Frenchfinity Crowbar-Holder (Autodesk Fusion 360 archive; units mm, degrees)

design "Crowbar-Holder" references "Base"
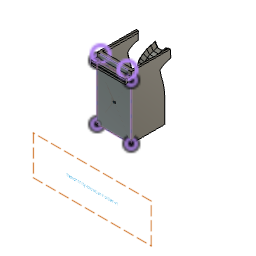
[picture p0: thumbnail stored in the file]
canvas "Canvas1"
sketch "Crowbar" plane through (0, 0, 0) normal (0, 1, 0) x axis (1, 0, 0)
  curve K1 (16, 63.0003) -> (-10, -19)
  curve K2 (34, 68) -> (-9.4189, -32.4164)
  curve K3 (2, -31) -> (-20.8379, -33.8327)
  line L1 (-10, -19) -> (-9.4189, -32.4164)
  line L2 (33.9629, 63.0003) -> (16, 63.0003)
  curve K4 (33.3578, 48.7031) -> (39.3178, 24.3477)
  curve K5 (2, -16) -> (-22, -22)
  curve K6 (23.0087, -3.4965) -> (4.9913, -16.5035)
  curve K7 (17.5692, 34.2662) -> (23.5165, 13.4506)
  curve K8 (32.9127, 49.5608) -> (35.158, 42.3075)
  point P8 (-9.4189, -32.4164)
  point P17 (33.9629, 63.0003)
  point P12 (36.3378, 36.5254)
  point P2 (-10, -19)
  point P3 (14, -10)
  point P5 (20.5429, 23.8584)
  point P13 (34.0354, 45.9341)
  midpoint P8 K3
  coincident K2 P17
  horizontal L2
  midpoint P12 K4
  midpoint P2 K5
  midpoint P3 K6
  midpoint P5 K7
  midpoint P13 K8
  coincident P13 K4
sketch "Holder" plane through (0, 0, 0) normal (0, 1, 0) x axis (1, 0, 0)
  line L1 (33.9629, 63.0003) -> (16, 63.0003)
  curve K1 (16, 63.0003) -> (-10, -19)
  line L2 (-10, -19) -> (-9.4189, -32.4164)
  curve K2 (34, 68) -> (-9.4189, -32.4164)
  line L3 (33.9629, 65.0003) -> (14.0747, 65.0003)
  curve K3 (14.0747, 65.0003) -> (-12.0688, -17.4556)
  line L4 (-12.0688, -17.4556) -> (-11.3233, -34.6679)
  curve K4 (36, 67.986) -> (-11.3233, -34.6679)
  line L5 (-10.0883, -16.9609) -> (-10, -19)
  line L6 (13.9986, 63.0003) -> (16, 63.0003)
  line L7 (-9.3321, -34.4209) -> (-9.4189, -32.4164)
  line L8 (35.9783, 65.0003) -> (33.9629, 65.0003)
  line L9 (35.9629, 63.0003) -> (33.9629, 63.0003)
  line L10 (33.9629, 73.0003) -> (6.3733, 73.0003)
  curve K5 (6.3733, 73.0003) -> (-20.3438, -11.2782)
  line L11 (-20.3438, -11.2782) -> (-18.9407, -43.6741)
  curve K6 (43.8182, 48.1303) -> (-18.9407, -43.6741)
  curve K7 (43.9998, 67.9301) -> (43.8182, 48.1303)
  line L12 (-10.4414, -8.8095) -> (-10.0883, -16.9609)
  line L13 (-8.9848, -42.4392) -> (-9.3321, -34.4209)
  line L14 (5.9931, 63.0003) -> (13.9986, 63.0003)
  line L15 (43.9632, 63.0003) -> (35.9629, 63.0003)
  line L16 (51.1083, -3.7697) -> (43.731, 0.4545)
  line L17 (41.8479, 1.5328) -> (43.731, 0.4545)
  line L18 (33.9629, 79.0003) -> (0.5973, 79.0003)
  curve K8 (0.5973, 79.0003) -> (8.1632, 5.9207)
  curve K9 (8.1632, 5.9207) -> (-26.5501, -6.6451)
  line L19 (-26.5501, -6.6451) -> (-24.6538, -50.4287)
  curve K10 (49.8231, 48.9354) -> (-24.6538, -50.4287)
  curve K11 (49.9996, 67.8881) -> (49.8231, 48.9354)
  line L20 (-10.706, -2.6999) -> (-10.4414, -8.8095)
  line L21 (-0.0108, 63.0003) -> (5.9931, 63.0003)
  point P4 (-10, -19)
  point P12 (-10, -19)
  point P13 (-10.0883, -16.9609)
  point P2 (16, 63.0003)
  point P14 (16, 63.0003)
  point P15 (13.9986, 63.0003)
  point P5 (-9.4189, -32.4164)
  point P16 (-9.4189, -32.4164)
  point P17 (-9.3321, -34.4209)
  point P18 (35.9783, 65.0003)
  point P3 (33.9629, 63.0003)
  point P19 (33.9629, 63.0003)
  point P20 (35.9629, 63.0003)
  point P27 (-10.4414, -8.8095)
  point P28 (-8.9848, -42.4392)
  point P29 (5.9931, 63.0003)
  point P30 (43.9632, 63.0003)
  point P31 (43.731, 0.4545)
  point P32 (51.1083, -3.7697)
  point P33 (41.8479, 1.5328)
  point P41 (-10.706, -2.6999)
  point P42 (-0.0108, 63.0003)
  coincident P4 P12
  coincident K3 P13
  parallel L4 L5
  coincident P2 P14
  coincident K3 P15
  parallel L1 L6
  coincident P5 P16
  coincident K4 P17
  parallel L2 L7
  coincident K4 P18
  parallel L3 L8
  coincident P3 P19
  coincident K4 P20
  parallel L1 L9
  coincident K5 P27
  parallel L5 L12
  coincident K6 P28
  parallel L7 L13
  coincident K5 P29
  parallel L6 L14
  coincident K7 P30
  parallel L9 L15
  coincident K4 P31
  coincident K6 P32
  coincident K2 P33
  parallel L16 L17
  coincident K9 P41
  parallel L12 L20
  coincident K8 P42
  parallel L14 L21
  dimension "d2" = -2
  dimension "d3" = -10
  dimension "d14" = -16
extrude "Extrude1" new body sketch "Holder" profile of K2 K4 K3 L9 K7 K5 L12 L14 L15 L16 L17 K9 L20 L21 along normal blind 22
sketch "Sketch3" plane through (-10.8026, 0, 0.4679) normal (-0.9991, 0, 0.0433) x axis (0, -1, 0)
  line L1 (0, 16.5085) -> (0, 2.2341)
  line L2 (-22, 16.5085) -> (0, 16.5085)
  line L3 (-22, 2.2341) -> (-22, 16.5085)
  line L4 (-11, 8.3494) -> (-11, 16.5085)
  line L5 (-11, 29.9609) -> (-11, 16.5085)
  line L6 (-11, 8.3494) -> (-11, 18.8494)
  line L7 (-0.3768, 18.8494) -> (-5.6884, 9.6494)
  line L8 (-5.6884, 28.0494) -> (-0.3768, 18.8494)
  line L9 (-16.3116, 28.0494) -> (-5.6884, 28.0494)
  line L10 (-21.6232, 18.8494) -> (-16.3116, 28.0494)
  line L11 (-16.3116, 9.6494) -> (-21.6232, 18.8494)
  line L12 (-5.6884, 9.6494) -> (-16.3116, 9.6494)
  line L13 (0, 2.2341) -> (-22, 2.2341)
  point P6 (-11, 16.5085)
  point P9 (-11, 18.8494)
  point P16 (-11, 18.8494)
  point P7 (-11, 8.3494)
  midpoint L2 P6
  perpendicular L2 L5
  coincident L5 P9
  coincident P9 P16
  dimension "d6" distance P7 P9 = 10.5
  dimension "d7" distance P16 L12 = 9.2
sweep "Sweep1" sketch "Sketch3" TwistAngle 0 TaperAngle 0
sketch "Sketch4" plane through (0, 22, 0) normal (0, 1, 0) x axis (-1, 0, 0)
  curve K1 (-43.8182, -48.1303) -> (-51.1083, 3.7697)
  curve K2 (-43.9632, -63.0003) -> (-43.8182, -48.1303)
  line L1 (-33.9629, -63.0003) -> (-43.9632, -63.0003)
  curve K3 (-41.8479, -1.5328) -> (-33.9629, -63.0003)
  line L2 (-51.1083, 3.7697) -> (-41.8479, -1.5328)
  curve K4 (-13.9986, -63.0003) -> (10.0883, 16.9609)
  line L3 (0.0108, -63.0003) -> (-13.9986, -63.0003)
  curve K5 (-8.1632, -5.9207) -> (0.0108, -63.0003)
  curve K6 (10.706, 2.6999) -> (-8.1632, -5.9207)
  line L4 (10.0883, 16.9609) -> (10.706, 2.6999)
  line L5 (-59.0437, 16.9609) -> (10.0883, 16.9609)
  line L6 (-43.9632, -63.0003) -> (0.0108, -63.0003)
  line L7 (-77.0255, -63.0003) -> (-43.9632, -63.0003)
  line L8 (-59.0437, -63.0003) -> (-59.0437, 16.9609)
  point P7 (10.0883, 16.9609)
  point P12 (10.0883, 16.9609)
  point P9 (0.0108, -63.0003)
  point P14 (0.0108, -63.0003)
  point P4 (-43.9632, -63.0003)
  point P15 (-43.9632, -63.0003)
  point P16 (-43.9632, -63.0003)
  point P18 (-59.0437, -63.0003)
  coincident P7 P12
  horizontal L5
  coincident P9 P14
  coincident P4 P15
  coincident P4 P16
  parallel L1 L7
  coincident L7 P18
  perpendicular L7 L8
extrude "Extrude2" add sketch "Sketch4" along normal blind 5
sketch "Sketch5" plane through (0, 22, 0) normal (0, -1, 0) x axis (1, 0, 0)
  curve K1 (13.9986, -63.0003) -> (-10.0883, 16.9609)
  line L1 (33.9629, -63.0003) -> (13.9986, -63.0003)
  curve K2 (41.8479, -1.5328) -> (33.9629, -63.0003)
  line L2 (51.1083, 3.7697) -> (41.8479, -1.5328)
  curve K3 (43.8182, -48.1303) -> (51.1083, 3.7697)
  curve K4 (43.9632, -63.0003) -> (43.8182, -48.1303)
  line L3 (59.0437, -63.0003) -> (43.9632, -63.0003)
  line L4 (59.0437, 16.9609) -> (59.0437, -63.0003)
  line L5 (-10.0883, 16.9609) -> (59.0437, 16.9609)
  curve K5 (43.8182, -48.1303) -> (51.1083, 3.7697)
  line L6 (41.8479, -1.5328) -> (51.1083, 3.7697)
  curve K6 (33.9629, -63.0003) -> (41.8479, -1.5328)
  line L7 (43.9632, -63.0003) -> (33.9629, -63.0003)
  curve K7 (43.9632, -63.0003) -> (43.8182, -48.1303)
  line L8 (51.1083, 16.9609) -> (51.1083, 3.7697)
  point P11 (51.1083, 3.7697)
  point P16 (51.1083, 3.7697)
  point P17 (51.1083, 16.9609)
  coincident P11 P16
  coincident L5 P17
  perpendicular L5 L8
extrude "Extrude3" add sketch "Sketch5" profile of K3 K4 L3 L4 L5 K5 K7 L8 along normal blind 50
extrude "Extrude4" add of existing geometry to an object
sketch "Sketch6" plane through (0, -28, 0) normal (0, -1, 0) x axis (1, 0, 0)
  line L1 (59.0437, -63.0003) -> (33.9629, -63.0003)
  line L2 (59.0437, 16.9609) -> (59.0437, -63.0003)
  line L3 (51.1083, 16.9609) -> (59.0437, 16.9609)
  line L4 (51.1083, 3.7697) -> (51.1083, 16.9609)
  line L5 (41.8479, -1.5328) -> (51.1083, 3.7697)
  curve K1 (41.8479, -1.5328) -> (33.9629, -63.0003)
  curve K2 (8.1632, -5.9207) -> (-0.0108, -63.0003)
  curve K3 (-10.706, 2.6999) -> (8.1632, -5.9207)
  line L6 (-10.0883, 16.9609) -> (-10.706, 2.6999)
  line L7 (59.0437, 16.9609) -> (-10.0883, 16.9609)
  line L8 (59.0437, -63.0003) -> (59.0437, 16.9609)
  line L9 (-0.0108, -63.0003) -> (59.0437, -63.0003)
extrude "Extrude5" add sketch "Sketch6" along normal blind 5
fillet "Fillet1" radius 2
component_insert "Component Insert"
sketch "Sketch7" plane through (0, 55.6118, 0) normal (0, 1, 0) x axis (-1, 0, 0)
  line L1 (0, 52.6059) -> (-47, 52.6059)
  line L2 (0, 60) -> (0, 52.6059)
  line L3 (-47, 60) -> (0, 60)
  line L4 (-47, 52.6059) -> (-47, 60)
  line L5 (-47, 60) -> (0, 60)
move "Move1"
move "Move2"
extrude "Extrude6" add of existing geometry to an object
extrude "Extrude7" add of existing geometry to an object
extrude "Extrude8" add of existing geometry blind 30
sketch "Text" plane through (0, 55.6118, 0) normal (0, -1, 0) x axis (1, 0, 0)
  dimension "d31" = 3
extrude "Extrude9" cut sketch "Text" against normal blind 2
sketch "Filename" plane through (0, 0, 0) normal (0, 1, 0) x axis (1, 0, 0)
  dimension "d34" = 5

design "Base"
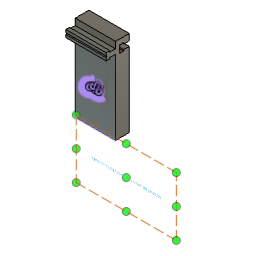
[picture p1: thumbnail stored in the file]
parameter "wall_anchor_height" = 60
parameter "wall_anchor_width" = 20
parameter "wall_anchor_angle" = 45
parameter "width_per_slot" = 40
parameter "slot_inner_width" = 8.5
parameter "slot_inner_height" = 4.5
parameter "slot_outer_width" = 5.6
parameter "slot_outer_height" = 6.5
parameter "slot_dept" = 15
parameter "print_tolerance" = 0.12
parameter "base_plate_thickness" = 16
parameter "base_plate_slot_height" = 50
parameter "wall_anchor_angle_rounded_border" = 1.5
parameter "base_plate_screw_hole_diameter" = 4
parameter "base_plate_screw_head_diameter" = 8
parameter "base_plate_screw_head_height" = 4
parameter "base_plate_screw_hole_side_distance" = 7
parameter "slot_screw_head_width" = 4.42 (= "4.3 mm + print_tolerance")
parameter "slot_screw_thread_width" = 2.12 (= "2 mm + print_tolerance")
parameter "slot_screw_head_height" = 2.12 (= "2 mm + print_tolerance")
parameter "width" = 47
parameter "filament_hole_width" = 1.7
parameter "plate_height" = 80
parameter "screw_plate_screw_head_widht" = 8
parameter "screw_plate_screw_head_height" = 4
parameter "screw_plate_screw_diameter" = 4
parameter "SkadisSlotW_1" = 5 comment "Skadis Slot Width"
parameter "SkadisSlotH_1" = 15 comment "Skadis Slot Height"
parameter "ClearanceHoriz_1" = 0.3 comment "Horizontal clearance for peg"
parameter "ClearanceVerticle_1" = 1 comment "Vertical clearance for peg"
parameter "PegW_1" = 4.7 (= "SkadisSlotW_1 - ClearanceHoriz_1") comment "Calculated Peg Width"
parameter "PegH_1" = 14 (= "SkadisSlotH_1 - ClearanceVerticle_1") comment "Calculated Peg Height"
parameter "PegD_1" = 5.2 (= "5 mm + 0.2 mm")
parameter "SkadisSlotW_2" = 5 comment "Skadis Slot Width"
parameter "SkadisSlotH_2" = 15 comment "Skadis Slot Height"
parameter "ClearanceHoriz_2" = 0.3 comment "Horizontal clearance for peg"
parameter "ClearanceVerticle_2" = 1 comment "Vertical clearance for peg"
parameter "PegW_2" = 4.7 (= "SkadisSlotW_2 - ClearanceHoriz_2") comment "Calculated Peg Width"
parameter "PegH_2" = 14 (= "SkadisSlotH_2 - ClearanceVerticle_2") comment "Calculated Peg Height"
parameter "PegD_2" = 5.2 (= "5 mm + 0.2 mm")
parameter "SkadisSlotW_3" = 5 comment "Skadis Slot Width"
parameter "SkadisSlotH_3" = 15 comment "Skadis Slot Height"
parameter "ClearanceHoriz_3" = 0.3 comment "Horizontal clearance for peg"
parameter "ClearanceVerticle_3" = 1 comment "Vertical clearance for peg"
parameter "PegW_3" = 4.7 (= "SkadisSlotW_3 - ClearanceHoriz_3") comment "Calculated Peg Width"
parameter "PegH_3" = 14 (= "SkadisSlotH_3 - ClearanceVerticle_3") comment "Calculated Peg Height"
parameter "PegD_3" = 5.2 (= "5 mm + 0.2 mm")
sketch "Side" plane through (0, 0, 0) normal (1, 0, 0) x axis (0, 1, 0)
  line L1 (39.6118, 0) -> (19.6118, 0)
  line L2 (39.6118, 60) -> (39.6118, 0)
  line L3 (19.6118, 60) -> (39.6118, 60)
  line L4 (19.6118, 0) -> (19.6118, 60)
  line L5 (39.6118, 39.6118) -> (0, 0)
  line L6 (56.0196, 0) -> (0, 0)
  point P1 (0, 0)
  point P6 (0, 0)
  point P7 (39.6118, 39.6118)
  point P2 (19.6118, 0)
  point P3 (39.6118, 0)
  point P5 (19.6118, 60)
  horizontal L1
  vertical L2
  horizontal L3
  vertical L4
  horizontal L6
  coincident P1 P6
  coincident L2 P7
  dimension "d4" distance P2 P3 = 20 (= "wall_anchor_width")
  dimension "d5" distance P2 P5 = 60 (= "wall_anchor_height")
  dimension "d6" angle L5 L6 = 45 (= "wall_anchor_angle")
extrude "Extrude1" new body sketch "Side" profile of L1 L2 L3 L4 L5 along normal blind 40 (= "width_per_slot")
sketch "Slot LeftToRight" plane through (0, 0, 0) normal (-1, 0, 0) x axis (0, -1, 0)
  line L1 (-19.6118, 60) -> (-19.6118, 19.6118)
  line L2 (-39.6118, 60) -> (-19.6118, 60)
  line L3 (-39.6118, 39.6118) -> (-39.6118, 60)
  line L4 (-19.6118, 19.6118) -> (-39.6118, 39.6118)
  line L5 (-39.6118, 52.6059) -> (-39.6118, 49.8059)
  line L6 (-39.6118, 47.0059) -> (-39.6118, 49.8059)
  line L7 (-33.1118, 52.6059) -> (-39.6118, 52.6059)
  line L8 (-28.6118, 49.8059) -> (-39.6118, 49.8059)
  line L9 (-28.6118, 54.0559) -> (-28.6118, 49.8059)
  line L10 (-33.1118, 54.0559) -> (-28.6118, 54.0559)
  line L11 (-33.1118, 52.6059) -> (-33.1118, 54.0559)
  line L12 (-28.6118, 45.5559) -> (-28.6118, 49.8059)
  line L13 (-33.1118, 45.5559) -> (-28.6118, 45.5559)
  line L14 (-33.1118, 47.0059) -> (-33.1118, 45.5559)
  line L15 (-33.1118, 47.0059) -> (-39.6118, 47.0059)
  point P6 (-39.6118, 49.8059)
  point P7 (-39.6118, 52.6059)
  point P17 (-39.6118, 47.0059)
  point P9 (-33.1118, 52.6059)
  point P16 (-33.1118, 47.0059)
  point P10 (-28.6118, 49.8059)
  point P13 (-28.6118, 49.8059)
  point P11 (-28.6118, 54.0559)
  point P14 (-28.6118, 45.5559)
  point P12 (-33.1118, 54.0559)
  point P15 (-33.1118, 45.5559)
  midpoint L3 P6
  parallel L3 L5
  parallel L3 L6
  perpendicular L3 L7
  perpendicular L6 L8
  perpendicular L8 L9
  perpendicular L9 L10
  symmetric P7 L8 P17
  symmetric P9 L8 P16
  symmetric P10 L8 P13
  symmetric L8 P11 P14
  symmetric L8 P12 P15
  dimension "d80" distance P6 P7 = 2.8 (= "slot_outer_width / 2")
  dimension "d82" distance P7 P9 = 6.5 (= "slot_outer_height")
  dimension "d84" distance P6 P10 = 11 (= "slot_outer_height + slot_inner_height")
  dimension "d85" distance P10 P11 = 4.25 (= "slot_inner_width / 2")
  dimension "d86" distance P11 P12 = 4.5 (= "slot_inner_height")
extrude "Extrude3" cut sketch "Slot LeftToRight" profile of L3 L5 L6 L7 L9 L10 L11 L12 L13 L14 L15 against normal blind 40 (magnitude of "width_per_slot * -1")
sketch "Plate" plane through (0, 39.6118, 0) normal (0, 1, 0) x axis (-1, 0, 0)
  line L1 (0, 39.6118) -> (-40, 39.6118)
  line L2 (-40, 60) -> (0, 60)
  line L3 (0, 10) -> (0, 60)
  line L4 (-40, 10) -> (-40, 60)
  line L5 (-40, 10) -> (0, 10)
  line L6 (-40, 47.0059) -> (0, 47.0059)
  line L7 (-40, 52.6059) -> (-40, 60)
  line L8 (0, 60) -> (0, 52.6059)
  line L9 (0, 52.6059) -> (-40, 52.6059)
  line L10 (-40, 60) -> (0, 60)
  line L11 (-40, 39.6118) -> (-40, 47.0059)
  line L12 (0, 47.0059) -> (0, 39.6118)
  point P2 (0, 60)
  point P3 (-40, 60)
  point P4 (0, 10)
  point P5 (-40, 10)
  perpendicular L1 L3
  perpendicular L1 L4
  dimension "d36" distance P2 P3 = 40 (= "width_per_slot")
  dimension "d37" distance P2 P4 = 50 (= "base_plate_slot_height")
  dimension "d39" distance P3 P5 = 50 (= "base_plate_slot_height")
extrude "Extrude6" new body sketch "Plate" profile of L1 L2 L3 L4 L5 L6 L7 L8 L9 L10 along normal blind 16 (= "base_plate_thickness") bodies "Base plate with slot"
sketch "Slot" plane through (0, 0, 0) normal (-1, 0, 0) x axis (0, -1, 0)
  line L1 (-19.6118, 60) -> (-19.6118, 19.6118)
  line L2 (-39.6118, 60) -> (-19.6118, 60)
  line L3 (-39.6118, 52.6059) -> (-39.6118, 60)
  line L4 (-33.1118, 52.6059) -> (-39.6118, 52.6059)
  line L5 (-33.1118, 54.0559) -> (-33.1118, 52.6059)
  line L6 (-28.6118, 54.0559) -> (-33.1118, 54.0559)
  line L7 (-28.6118, 45.5559) -> (-28.6118, 54.0559)
  line L8 (-33.1118, 45.5559) -> (-28.6118, 45.5559)
  line L9 (-33.1118, 47.0059) -> (-33.1118, 45.5559)
  line L10 (-39.6118, 47.0059) -> (-33.1118, 47.0059)
  line L11 (-39.6118, 39.6118) -> (-39.6118, 47.0059)
  line L12 (-19.6118, 19.6118) -> (-39.6118, 39.6118)
  line L13 (-33.1118, 52.6059) -> (-39.6118, 52.6059)
  line L14 (-33.1118, 54.0559) -> (-33.1118, 52.6059)
  line L15 (-28.6118, 54.0559) -> (-33.1118, 54.0559)
  line L16 (-28.6118, 45.5559) -> (-28.6118, 54.0559)
  line L17 (-33.1118, 45.5559) -> (-28.6118, 45.5559)
  line L18 (-33.1118, 47.0059) -> (-33.1118, 45.5559)
  line L19 (-39.6118, 47.0059) -> (-33.1118, 47.0059)
  line L20 (-39.6118, 10) -> (-39.6118, 60)
  line L21 (-32.9918, 52.4859) -> (-39.6118, 52.4859)
  line L22 (-32.9918, 53.9359) -> (-32.9918, 52.4859)
  line L23 (-28.7318, 53.9359) -> (-32.9918, 53.9359)
  line L24 (-28.7318, 45.6759) -> (-28.7318, 53.9359)
  line L25 (-32.9918, 45.6759) -> (-28.7318, 45.6759)
  line L26 (-32.9918, 47.1259) -> (-32.9918, 45.6759)
  line L27 (-39.6118, 47.1259) -> (-32.9918, 47.1259)
  line L28 (-33.1118, 52.6059) -> (-39.6118, 52.6059)
  line L29 (-33.1118, 52.6059) -> (-33.1118, 54.0559)
  line L30 (-28.6118, 54.0559) -> (-33.1118, 54.0559)
  line L31 (-28.6118, 45.5559) -> (-28.6118, 54.0559)
  line L32 (-33.1118, 45.5559) -> (-28.6118, 45.5559)
  line L33 (-33.1118, 47.0059) -> (-33.1118, 45.5559)
  line L34 (-39.6118, 47.0059) -> (-33.1118, 47.0059)
  line L35 (-39.6118, 47.0059) -> (-39.6118, 52.6059)
  line L36 (-49.1118, 52.6059) -> (-55.6118, 52.6059)
  line L37 (-49.1118, 52.6059) -> (-49.1118, 54.0559)
  line L38 (-44.6118, 54.0559) -> (-49.1118, 54.0559)
  line L39 (-44.6118, 45.5559) -> (-44.6118, 54.0559)
  line L40 (-49.1118, 45.5559) -> (-44.6118, 45.5559)
  line L41 (-49.1118, 47.0059) -> (-49.1118, 45.5559)
  line L42 (-55.6118, 47.0059) -> (-49.1118, 47.0059)
  line L43 (-55.6118, 47.0059) -> (-55.6118, 52.6059)
  point P15 (-39.6118, 52.6059)
  point P33 (-39.6118, 52.6059)
  point P16 (-33.1118, 52.6059)
  point P34 (-33.1118, 52.6059)
  point P17 (-33.1118, 54.0559)
  point P35 (-33.1118, 54.0559)
  point P36 (-33.1118, 52.6059)
  point P18 (-28.6118, 54.0559)
  point P37 (-28.6118, 54.0559)
  point P19 (-28.6118, 45.5559)
  point P38 (-28.6118, 45.5559)
  point P10 (-28.6118, 45.5559)
  point P39 (-28.6118, 45.5559)
  point P11 (-33.1118, 45.5559)
  point P40 (-33.1118, 45.5559)
  point P41 (-33.1118, 45.5559)
  point P12 (-33.1118, 47.0059)
  point P42 (-33.1118, 47.0059)
  point P21 (-33.1118, 47.0059)
  point P43 (-33.1118, 47.0059)
  point P22 (-39.6118, 47.0059)
  point P44 (-39.6118, 47.0059)
  point P45 (-39.6118, 52.6059)
  point P46 (-39.6118, 47.0059)
  coincident P15 P33
  coincident P16 P34
  coincident P17 P35
  coincident P16 P36
  coincident P18 P37
  coincident P19 P38
  coincident P10 P39
  coincident P11 P40
  coincident P11 P41
  coincident P12 P42
  coincident P21 P43
  coincident P22 P44
  coincident P15 P45
  coincident P22 P46
  dimension "d91" = 0.12 (= "print_tolerance")
  dimension "d96" R-Pattern1-uDistance = -16 (= "base_plate_thickness * -1")
  dimension "d97" R-Pattern1-vDistance = 0
extrude "Extrude7" add sketch "Slot" profile of L20 L24 L23 L27 L22 L25 L26 L21 against normal blind 40 (magnitude of "width_per_slot * -1")
extrude "Extrude8" cut sketch "Slot" profile of L36 L37 L38 L39 L40 L41 L42 L43 no distance stored
sketch "Sketch3" plane through (0, 0, 0) normal (-1, 0, 0) x axis (0, -1, 0)
  line L1 (-32.9918, 47.1259) -> (-39.6118, 47.1259)
  line L2 (-32.9918, 45.6759) -> (-32.9918, 47.1259)
  line L3 (-28.7318, 45.6759) -> (-32.9918, 45.6759)
  line L4 (-28.7318, 53.9359) -> (-28.7318, 45.6759)
  line L5 (-32.9918, 53.9359) -> (-28.7318, 53.9359)
  line L6 (-32.9918, 52.4859) -> (-32.9918, 53.9359)
  line L7 (-39.6118, 52.4859) -> (-32.9918, 52.4859)
  line L8 (-44.6118, 45.5559) -> (-44.6118, 54.0559)
  line L9 (-32.9918, 52.4859) -> (-39.6118, 52.4859)
  line L10 (-32.9918, 53.9359) -> (-32.9918, 52.4859)
  line L11 (-28.7318, 53.9359) -> (-32.9918, 53.9359)
  line L12 (-28.7318, 45.6759) -> (-28.7318, 53.9359)
  line L13 (-32.9918, 45.6759) -> (-28.7318, 45.6759)
  line L14 (-32.9918, 47.1259) -> (-32.9918, 45.6759)
  line L15 (-39.6118, 47.1259) -> (-32.9918, 47.1259)
  line L16 (-39.6118, 47.1259) -> (-39.6118, 52.4859)
  line L17 (-55.6118, 52.4859) -> (-48.9918, 52.4859)
  line L18 (-48.9918, 52.4859) -> (-48.9918, 53.9359)
  line L19 (-48.9918, 53.9359) -> (-44.7318, 53.9359)
  line L20 (-44.7318, 45.6759) -> (-44.7318, 53.9359)
  line L21 (-48.9918, 45.6759) -> (-44.7318, 45.6759)
  line L22 (-48.9918, 47.1259) -> (-48.9918, 45.6759)
  line L23 (-55.6118, 47.1259) -> (-48.9918, 47.1259)
  line L24 (-55.6118, 47.1259) -> (-55.6118, 52.4859)
  line L25 (-55.6118, 47.0059) -> (-49.1118, 47.0059)
  line L26 (-55.6118, 10) -> (-55.6118, 47.0059)
  line L27 (-39.6118, 10) -> (-55.6118, 10)
  line L28 (-39.6118, 47.1259) -> (-39.6118, 10)
  line L29 (-39.6118, 60) -> (-39.6118, 52.4859)
  line L30 (-55.6118, 60) -> (-39.6118, 60)
  line L31 (-55.6118, 52.6059) -> (-55.6118, 60)
  line L32 (-49.1118, 52.6059) -> (-55.6118, 52.6059)
  line L33 (-49.1118, 54.0559) -> (-49.1118, 52.6059)
  line L34 (-44.6118, 54.0559) -> (-49.1118, 54.0559)
  line L35 (-49.1118, 45.5559) -> (-44.6118, 45.5559)
  line L36 (-49.1118, 47.0059) -> (-49.1118, 45.5559)
  point P9 (-39.6118, 52.4859)
  point P20 (-39.6118, 52.4859)
  point P19 (-39.6118, 47.1259)
  point P21 (-39.6118, 47.1259)
  coincident P9 P20
  coincident P19 P21
  dimension "d105" R-Pattern1-vDistance = 0
extrude "Extrude3" new body sketch "Sketch3" profile of L17 L18 L19 L20 L21 L22 L23 L24 against normal blind 40 (magnitude of "width_per_slot * -1")
sketch "Screw hole" plane through (0, 28.6118, 0) normal (0, 1, 0) x axis (-1, 0, 0)
  line L1 (0, 54.0559) -> (0, 45.5559)
  line L2 (-40, 54.0559) -> (0, 54.0559)
  line L3 (-40, 45.5559) -> (-40, 54.0559)
  line L4 (0, 45.5559) -> (-40, 45.5559)
  line L5 (0, 45.5559) -> (-40, 54.0559)
  line L6 (-40, 45.5559) -> (0, 54.0559)
  circle C1 centre (-20, 49.8059) radius 2.21
  circle C2 centre (-20, 49.8059) radius 1.06
  point P4 (-40, 54.0559)
  point P6 (-40, 54.0559)
  point P2 (0, 45.5559)
  point P7 (0, 45.5559)
  point P3 (0, 54.0559)
  point P8 (0, 54.0559)
  point P5 (-40, 45.5559)
  point P9 (-40, 45.5559)
  point P10 (-20, 49.8059)
  coincident P4 P6
  coincident P2 P7
  coincident P3 P8
  coincident P5 P9
  midpoint L5 P10
  concentric C1 C2
  dimension "d119" diameter C1 = 4.42 (= "slot_screw_head_width")
  dimension "d120" diameter C2 = 2.12 (= "slot_screw_thread_width")
extrude "Extrude4" cut sketch "Screw hole" profile of C2 against normal blind 2000
extrude "Extrude5" cut sketch "Screw hole" profile of C1 C2 no distance stored
fillet "Fillet1" radius 1.5 (= "wall_anchor_angle_rounded_border")
work_plane "WorkPlane1" sketch "Slot LeftToRight" AlongDistance -20 (= "-width_per_slot / 2")
sketch "Screw head" plane through (20, 0, 0) normal (-1, 0, 0) x axis (0, -1, 0)
  line L1 (-28.6118, 52.0159) -> (-28.6118, 47.5959)
  line L2 (-26.4918, 52.0159) -> (-26.4918, 47.5959)
  line L3 (-26.4918, 48.7459) -> (-26.4918, 50.8659)
  line L4 (-26.4918, 50.8659) -> (-28.6118, 52.0159)
  line L5 (-26.4918, 52.0159) -> (-28.6118, 52.0159)
  point P3 (-28.6118, 52.0159)
  point P8 (-28.6118, 52.0159)
  point P6 (-26.4918, 50.8659)
  point P9 (-26.4918, 50.8659)
  point P10 (-28.6118, 52.0159)
  point P5 (-26.4918, 52.0159)
  point P11 (-26.4918, 52.0159)
  coincident P3 P8
  coincident P6 P9
  coincident P3 P10
  coincident P5 P11
revolve "Revolve1" sketch "Screw head" AlongAngle 360
rectangular_pattern "R-Pattern2" countU 1 (= "floor(( width / mm ) / ( width_per_slot / cm * 10 ))") uSpaceDistance 40 (= "width_per_slot") vSpaceDistance 0
work_plane "WorkPlane2"
extrude "Extrude12" new body of existing geometry no distance stored
mirror "Mirror3" mirrorStitchTolerance 0.1
sketch "filename" plane through (0, 19.6118, 0) normal (0, -1, 0) x axis (1, 0, 0)
  dimension "d216" = 3
sketch "Text" plane through (0, 19.6118, 0) normal (0, -1, 0) x axis (1, 0, 0)
  line L1 (43.5, 60) -> (43.5, 23.2332)
  line L2 (40, 23.2332) -> (40, 60)
  line L3 (43.5, 23.2332) -> (40, 23.2332)
  line L4 (43.5, 60) -> (43.5, 23.2332)
  line L5 (40, 60) -> (43.5, 60)
  line L6 (0, 60) -> (0, 23.2332)
  line L7 (-3.5, 60) -> (0, 60)
  line L8 (-3.5, 23.2332) -> (-3.5, 60)
  line L9 (0, 23.2332) -> (-3.5, 23.2332)
  curve K1
  curve K2
  curve K3
  curve K4
  line L10 (80, 60) -> (40, 60)
  point P4 (43.5, 23.2332)
  point P2 (-3.5, 60)
  coincident P4
  coincident P2
  parallel K3 L10
  dimension "d229" Text1-Height = 3
extrude "Extrude19" cut sketch "Text" against normal blind 2
extrude "Extrude14" cut of existing geometry blind 3.5 (= "( width_per_slot - width ) / -2")
extrude "Extrude15" cut of existing geometry blind 3.5 (= "( width_per_slot - width ) / -2")
extrude "Extrude9" cut of existing geometry blind -39 (= "-width_per_slot + 1 mm")
extrude "Extrude10" add of existing geometry blind 46 (= "width - 1 mm")
extrude "Extrude13" cut of existing geometry blind -30
extrude "Extrude14" add of existing geometry blind 80 (= "plate_height")
sketch "Sketch7" plane through (0, 39.6118, 0) normal (0, -1, 0) x axis (1, 0, 0)
  dimension "d236" = 3
extrude "Extrude11" cut sketch "Sketch7" against normal blind 2
sketch "File name" plane through (0, 39.6118, 0) normal (0, -1, 0) x axis (1, 0, 0)
  line L1 (0, 47.1259) -> (47, 47.1259)
  line L2 (0, -40) -> (0, 47.1259)
  line L3 (47, 47.1259) -> (47, -40)
  curve K1
  curve K2
  curve K3
  curve K4
  line L4 (47, -40) -> (0, -40)
  curve K5 (21.0617, 1.5882) -> (21.4014, 1.3488)
  line L5 (16.2752, -1.111) -> (16.6436, -1.111)
  line L6 (18.9744, -0.2781) -> (18.9744, 0.9108)
  line L7 (18.6061, -0.2781) -> (18.9744, -0.2781)
  curve K6 (20.9512, 1.9606) -> (21.0617, 1.5882)
  curve K7 (21.1866, 2.5111) -> (20.9512, 1.9606)
  line L8 (16.6436, -1.111) -> (16.6436, -0.053)
  curve K8 (16.6436, -0.053) -> (16.883, -0.2495)
  curve K9 (26.9574, -0.0182) -> (27.6388, -0.3293)
  curve K10 (26.6606, 1.2014) -> (26.9574, -0.0182)
  curve K11 (28.1832, -0.1533) -> (28.5085, 0.3481)
  curve K12 (27.6388, -0.3293) -> (28.1832, -0.1533)
  curve K13 (23.4621, -0.0182) -> (24.1436, -0.3293)
  curve K14 (23.1654, 1.2014) -> (23.4621, -0.0182)
  curve K15 (24.5672, 2.6359) -> (24.1436, 2.7342)
  curve K16 (24.868, 2.3556) -> (24.5672, 2.6359)
  curve K17 (25.0542, 1.9095) -> (24.868, 2.3556)
  curve K18 (25.1218, 1.2014) -> (25.0542, 1.9095)
  curve K19 (25.0133, 0.3481) -> (25.1218, 1.2014)
  curve K20 (24.6879, -0.1533) -> (25.0133, 0.3481)
  curve K21 (24.1436, -0.3293) -> (24.6879, -0.1533)
  curve K22 (19.2405, 1.5411) -> (19.5495, 1.6271)
  curve K23 (19.0358, 1.3119) -> (19.2405, 1.5411)
  curve K24 (18.9744, 0.9108) -> (19.0358, 1.3119)
  line L9 (25.7029, 4.404) -> (26.0815, 4.404)
  curve K25 (25.8421, 5.2594) -> (25.7029, 4.404)
  curve K26 (26.2227, 6.2253) -> (25.8421, 5.2594)
  dimension "d239" Text1-Height = 3
sketch "Sketch4" plane through (40, 0, 0) normal (1, 0, 0) x axis (0, 1, 0)
  line L1 (44.7318, 53.9359) -> (48.9918, 53.9359)
  line L2 (44.7318, 45.6759) -> (44.7318, 53.9359)
  line L3 (48.9918, 45.6759) -> (44.7318, 45.6759)
  line L4 (48.9918, 47.1259) -> (48.9918, 45.6759)
  line L5 (55.6118, 47.1259) -> (48.9918, 47.1259)
  line L6 (55.6118, 52.4859) -> (55.6118, 47.1259)
  line L7 (48.9918, 52.4859) -> (55.6118, 52.4859)
  line L8 (48.9918, 53.9359) -> (48.9918, 52.4859)
  circle C1 centre (44.7318, 49.8059) radius 0.85
  point P10 (44.7318, 49.8059)
  midpoint L2 P10
  dimension "d241" diameter C1 = 1.7 (= "filament_hole_width")
extrude "Extrude4" cut sketch "Sketch4" profile of L2 C1 no distance stored
sketch "Sketch15" plane through (-3.5, 0, 0) normal (-1, 0, 0) x axis (0, -1, 0)
  line L1 (-19.6118, 60) -> (-19.6118, 23.2332)
  line L2 (-39.6118, 60) -> (-19.6118, 60)
  line L3 (-39.6118, 52.6059) -> (-39.6118, 60)
  line L4 (-33.1118, 52.6059) -> (-39.6118, 52.6059)
  line L5 (-33.1118, 54.0559) -> (-33.1118, 52.6059)
  line L6 (-28.6118, 54.0559) -> (-33.1118, 54.0559)
  line L7 (-28.6118, 45.5559) -> (-28.6118, 54.0559)
  line L8 (-33.1118, 45.5559) -> (-28.6118, 45.5559)
  line L9 (-33.1118, 47.0059) -> (-33.1118, 45.5559)
  line L10 (-39.6118, 47.0059) -> (-33.1118, 47.0059)
  line L11 (-39.6118, 39.6118) -> (-39.6118, 47.0059)
  line L12 (-22.1725, 22.1725) -> (-39.6118, 39.6118)
  arc A1 centre (-21.1118, 23.2332) radius 1.5 clockwise from (-19.6118, 23.2332) to (-22.1725, 22.1725)
  circle C1 centre (-28.6118, 49.8059) radius 0.85
  point P16 (-28.6118, 49.8059)
  midpoint L7 P16
  dimension "d244" diameter C1 = 1.7 (= "filament_hole_width")
sketch "Sketch9" plane through (47, 0, 0) normal (1, 0, 0) x axis (0, 1, 0)
  line L1 (49.1118, 47.0059) -> (55.6118, 47.0059)
  line L2 (49.1118, 45.5559) -> (49.1118, 47.0059)
  line L3 (44.6118, 45.5559) -> (49.1118, 45.5559)
  line L4 (44.6118, 54.0559) -> (44.6118, 45.5559)
  line L5 (49.1118, 54.0559) -> (44.6118, 54.0559)
  line L6 (49.1118, 52.6059) -> (49.1118, 54.0559)
  line L7 (55.6118, 52.6059) -> (49.1118, 52.6059)
  line L8 (55.6118, 47.0059) -> (55.6118, -40)
  line L9 (39.6118, 60) -> (55.6118, 60)
  line L10 (39.6118, 52.4859) -> (39.6118, 60)
  line L11 (32.9918, 52.4859) -> (39.6118, 52.4859)
  line L12 (32.9918, 53.9359) -> (32.9918, 52.4859)
  line L13 (28.7318, 53.9359) -> (32.9918, 53.9359)
  line L14 (28.7318, 45.6759) -> (28.7318, 53.9359)
  line L15 (32.9918, 45.6759) -> (28.7318, 45.6759)
  line L16 (32.9918, 47.1259) -> (32.9918, 45.6759)
  line L17 (39.6118, 47.1259) -> (32.9918, 47.1259)
  line L18 (55.6118, 60) -> (55.6118, 52.6059)
  line L19 (39.6118, -40) -> (39.6118, 47.1259)
  line L20 (55.6118, -40) -> (39.6118, -40)
  circle C1 centre (28.7318, 49.8059) radius 0.85
  circle C2 centre (44.6118, 49.8059) radius 0.85
  point P20 (28.7318, 49.8059)
  point P21 (44.6118, 49.8059)
  midpoint L14 P20
  midpoint L4 P21
  dimension "d247" diameter C1 = 1.7 (= "filament_hole_width")
  dimension "d250" diameter C2 = 1.7 (= "filament_hole_width")
extrude "Extrude12" cut sketch "Sketch9" profile of L4 L14 C1 C2 no distance stored
sketch "Sketch16" plane through (0, 19.6118, 0) normal (0, -1, 0) x axis (1, 0, 0)
  dimension "d253" = 3
extrude "Extrude22" cut sketch "Sketch16" against normal blind 2
extrude "Extrude23" cut sketch "Sketch15" profile of L7 C1 against normal blind 260 and along normal blind 80
sketch "Sketch17" plane through (0, 19.6118, 0) normal (0, -1, 0) x axis (1, 0, 0)
  line L1 (0, 60) -> (40, 60)
  line L2 (40, 23.2332) -> (0, 23.2332)
  curve K1
  curve K2
  curve K3
  curve K4
  line L3 (40, 60) -> (40, 23.2332)
  line L4 (0, 23.2332) -> (0, 60)
  curve K5 (14.0832, 42.1328) -> (14.4328, 42.3871)
  curve K6 (13.6968, 41.9419) -> (14.0832, 42.1328)
  curve K7 (14.2359, 42.6507) -> (13.6962, 42.2979)
  curve K8 (14.5627, 43.0523) -> (14.2359, 42.6507)
  curve K9 (17.9487, 40.9457) -> (17.8368, 40.4974)
  curve K10 (20.4689, 40.2313) -> (21.1261, 39.997)
  curve K11 (20.1712, 40.8407) -> (20.4689, 40.2313)
  curve K12 (20.755, 40.4384) -> (20.5395, 40.8904)
  curve K13 (21.1277, 40.3019) -> (20.755, 40.4384)
  curve K14 (21.5653, 40.4827) -> (21.1277, 40.3019)
  curve K15 (21.7447, 40.9291) -> (21.5653, 40.4827)
  curve K16 (21.5783, 41.3463) -> (21.7447, 40.9291)
  curve K17 (21.1565, 41.5114) -> (21.5783, 41.3463)
  curve K18 (20.8967, 41.47) -> (21.1565, 41.5114)
  curve K19 (20.9965, 41.7894) -> (20.9371, 41.7934)
  curve K20 (21.4199, 41.9129) -> (20.9965, 41.7894)
  curve K21 (21.6076, 42.2917) -> (21.4199, 41.9129)
  curve K22 (21.4699, 42.6271) -> (21.6076, 42.2917)
  curve K23 (21.1157, 42.7596) -> (21.4699, 42.6271)
  curve K24 (20.7578, 42.624) -> (21.1157, 42.7596)
  curve K25 (20.5742, 42.2185) -> (20.7578, 42.624)
  curve K26 (20.5119, 42.8569) -> (20.2058, 42.2834)
  curve K27 (21.107, 43.0625) -> (20.5119, 42.8569)
  curve K28 (21.5595, 42.9568) -> (21.107, 43.0625)
  curve K29 (21.875, 42.6707) -> (21.5595, 42.9568)
  curve K30 (21.9861, 42.2841) -> (21.875, 42.6707)
  curve K31 (21.8823, 41.93) -> (21.9861, 42.2841)
  curve K32 (21.5737, 41.6757) -> (21.8823, 41.93)
  curve K33 (21.9875, 41.4206) -> (21.5737, 41.6757)
  curve K34 (22.1356, 40.9379) -> (21.9875, 41.4206)
  curve K35 (21.8501, 40.2703) -> (22.1356, 40.9379)
  curve K36 (21.1261, 39.997) -> (21.8501, 40.2703)
  curve K37 (26.2927, 40.3181) -> (26.9747, 40.0081)
  curve K38 (25.9941, 41.5373) -> (26.2927, 40.3181)
  curve K39 (26.1013, 42.3928) -> (25.9941, 41.5373)
  curve K40 (26.4259, 42.8947) -> (26.1013, 42.3928)
  curve K41 (26.9699, 43.0715) -> (26.4259, 42.8947)
  curve K42 (27.3937, 42.974) -> (26.9699, 43.0715)
  curve K43 (27.6949, 42.6941) -> (27.3937, 42.974)
  curve K44 (27.8818, 42.2482) -> (27.6949, 42.6941)
  curve K45 (27.9505, 41.5403) -> (27.8818, 42.2482)
  curve K46 (27.8433, 40.6868) -> (27.9505, 41.5403)
  curve K47 (27.5187, 40.1849) -> (27.8433, 40.6868)
  curve K48 (26.9747, 40.0081) -> (27.5187, 40.1849)
  curve K49 (23.991, 42.6617) -> (23.4622, 41.8751)
  curve K50 (23.896, 41.9188) -> (24.4636, 42.73)
  curve K51 (23.4638, 40.8785) -> (23.896, 41.9188)
  curve K52 (23.3238, 40.0536) -> (23.4638, 40.8785)
  curve K53 (23.0831, 40.9086) -> (22.9453, 40.053)
  curve K54 (23.4622, 41.8751) -> (23.0831, 40.9086)
  curve K55 (28.6236, 40.3217) -> (29.3055, 40.0117)
  curve K56 (28.325, 41.5409) -> (28.6236, 40.3217)
  curve K57 (28.4321, 42.3964) -> (28.325, 41.5409)
  curve K58 (28.7567, 42.8983) -> (28.4321, 42.3964)
  curve K59 (29.3008, 43.0751) -> (28.7567, 42.8983)
  curve K60 (29.7245, 42.9776) -> (29.3008, 43.0751)
  curve K61 (30.0258, 42.6977) -> (29.7245, 42.9776)
  curve K62 (30.2127, 42.2519) -> (30.0258, 42.6977)
  curve K63 (30.2813, 41.5439) -> (30.2127, 42.2519)
  curve K64 (30.1742, 40.6904) -> (30.2813, 41.5439)
  curve K65 (29.8496, 40.1885) -> (30.1742, 40.6904)
  curve K66 (29.3055, 40.0117) -> (29.8496, 40.1885)
  curve K67 (12.1949, 40.4702) -> (12.0551, 40.9079)
  curve K68 (12.3314, 40.8838) -> (12.1949, 40.4702)
  circle C1 centre (20, 49.8059) radius 1.06
  point P2 (40, 23.2332)
  point P4 (0, 60)
  coincident P2
  coincident P4
  dimension "d258" Text1-Height = 3
extrude "Extrude24" cut sketch "Sketch17" against normal blind 2
extrude "Extrude26" cut sketch "Text" against normal blind 2
extrude "Extrude27" cut sketch "Text" against normal blind 2
sketch "Sketch1" plane through (47, 0, 0) normal (1, 0, 0) x axis (0, 1, 0)
  line L1 (28.7318, 45.6759) -> (28.7318, 48.9559)
  line L2 (32.9918, 45.6759) -> (28.7318, 45.6759)
  line L3 (32.9918, 47.1259) -> (32.9918, 45.6759)
  line L4 (39.6118, 47.1259) -> (32.9918, 47.1259)
  line L5 (39.6118, -40) -> (39.6118, 47.1259)
  line L6 (55.6118, -40) -> (39.6118, -40)
  line L7 (55.6118, 47.0059) -> (55.6118, -40)
  line L8 (49.1118, 47.0059) -> (55.6118, 47.0059)
  line L9 (49.1118, 45.5559) -> (49.1118, 47.0059)
  line L10 (44.6118, 45.5559) -> (49.1118, 45.5559)
  line L11 (44.6118, 48.9559) -> (44.6118, 45.5559)
  line L12 (44.6118, 54.0559) -> (44.6118, 50.6559)
  line L13 (49.1118, 54.0559) -> (44.6118, 54.0559)
  line L14 (49.1118, 52.6059) -> (49.1118, 54.0559)
  line L15 (55.6118, 52.6059) -> (49.1118, 52.6059)
  line L16 (55.6118, 60) -> (55.6118, 52.6059)
  line L17 (39.6118, 60) -> (55.6118, 60)
  line L18 (39.6118, 52.4859) -> (39.6118, 60)
  line L19 (32.9918, 52.4859) -> (39.6118, 52.4859)
  line L20 (32.9918, 53.9359) -> (32.9918, 52.4859)
  line L21 (28.7318, 53.9359) -> (32.9918, 53.9359)
  line L22 (28.7318, 50.6559) -> (28.7318, 53.9359)
  line L23 (55.6118, 47.0059) -> (55.6118, -40)
  line L24 (39.6118, 47.1259) -> (39.6118, 52.4859)
  arc A1 centre (28.7318, 49.8059) radius 0.85 clockwise from (28.7318, 50.6559) to (28.7318, 48.9559)
  arc A2 centre (44.6118, 49.8059) radius 0.85 clockwise from (44.6118, 48.9559) to (44.6118, 50.6559)
  point P24 (39.6118, 52.4859)
  point P30 (39.6118, 52.4859)
  point P8 (39.6118, 47.1259)
  point P31 (39.6118, 47.1259)
  coincident P24 P30
  coincident P8 P31
extrude "Extrude1" new body sketch "Sketch1" profile of L5 L6 L7 L8 L9 L10 L11 A2 L12 L13 L14 L15 L16 L17 L18 L23 L24 along normal blind 47 (= "width") bodies "Screw plate"
sketch "Screw Base" plane through (0, 55.6118, 0) normal (0, 1, 0) x axis (-1, 0, 0)
  line L1 (-47, 47.0059) -> (-47, -40)
  line L2 (-94, 47.0059) -> (-47, 47.0059)
  line L3 (-94, -40) -> (-94, 47.0059)
  line L4 (-47, -40) -> (-94, -40)
  line L5 (-70.5, -40) -> (-70.5, 47.0059)
  line L6 (-70.5, 35.0059) -> (-70.5, 47.0059)
  circle C1 centre (-70.5, 35.0059) radius 4
  circle C2 centre (-70.5, 35.0059) radius 2
  point P6 (-70.5, 47.0059)
  point P7 (-70.5, -40)
  point P8 (-70.5, 35.0059)
  point P9 (-70.5, 35.0059)
  midpoint L2 P6
  midpoint L4 P7
  perpendicular L2 L6
  coincident P8 P9
  concentric C1 C2
  dimension "d276" distance P6 P8 = 12
  dimension "d280" diameter C1 = 8 (= "screw_plate_screw_head_widht")
  dimension "d281" diameter C2 = 4 (= "base_plate_screw_hole_diameter")
work_plane "WorkPlane1" sketch "Screw Base" AlongDistance -4 (= "screw_plate_screw_head_height * -1")
sketch "Screw Head" plane through (0, 51.6118, 0) normal (0, 1, 0) x axis (1, 0, 0)
  circle C1 centre (70.5, -35.0059) radius 2
extrude "Extrude2" new body sketch "Screw Head" to an object bodies "Screw hole"
loft "Loft1" sketch "Screw Head" + "Screw Base"
rectangular_pattern "R-Pattern1" countU 1 (= "floor(width / 30 / mm)") uSpaceDistance 30 vSpaceDistance 62 (= "plate_height - 18 mm") bodies "Screw hole (3)", "Screw hole (12)"
split "Split1" bodies "Screw plate (2)", "Screw plate"
sketch "Text" plane through (0, 39.6118, 0) normal (0, -1, 0) x axis (1, 0, 0)
  dimension "d289" = 3
sketch "Filename" plane through (0, 0, 0) normal (0, 1, 0) x axis (1, 0, 0)
  dimension "d290" = 5
extrude "Extrude3" cut sketch "Text" against normal blind 2
sketch "Sketch6" plane through (0, 0, 0) normal (0, 1, 0) x axis (1, 0, 0)
  dimension "d293" = 5
sketch "Sketch1" plane through (204, 0, 0) normal (1, 0, 0) x axis (0, 1, 0)
  line L1 (44.6118, 54.0559) -> (44.6118, 50.6559)
  line L2 (49.1118, 54.0559) -> (44.6118, 54.0559)
  line L3 (49.1118, 52.6059) -> (49.1118, 54.0559)
  line L4 (55.6118, 52.6059) -> (49.1118, 52.6059)
  line L5 (55.6118, 60) -> (55.6118, 52.6059)
  line L6 (39.6118, 60) -> (55.6118, 60)
  line L7 (39.6118, -40) -> (39.6118, 60)
  line L8 (55.6118, -40) -> (39.6118, -40)
  line L9 (55.6118, 47.0059) -> (55.6118, -40)
  line L10 (49.1118, 47.0059) -> (55.6118, 47.0059)
  line L11 (49.1118, 45.5559) -> (49.1118, 47.0059)
  line L12 (44.6118, 45.5559) -> (49.1118, 45.5559)
  line L13 (44.6118, 48.9559) -> (44.6118, 45.5559)
  arc A1 centre (44.6118, 49.8059) radius 0.85 clockwise from (44.6118, 48.9559) to (44.6118, 50.6559)
extrude "Extrude1" new body sketch "Sketch1" along normal blind 47 (= "width")
position "Position1"
sketch "Sketch1" plane through (0, 0, 0) normal (0, 1, 0) x axis (1, 0, 0)
  line L1 (-2.35, 22.35) -> (-2.35, 31.65)
  line L2 (2.35, 31.65) -> (2.35, 22.35)
  line L3 (0, 20) -> (0, 34)
  arc A1 centre (0, 22.35) radius 2.35 clockwise from (2.35, 22.35) to (-2.35, 22.35)
  arc A2 centre (0, 28.85) radius 2.35 clockwise from (2.35, 28.85) to (-2.35, 28.85)
  arc A3 centre (0, 31.65) radius 2.35 clockwise from (-2.35, 31.65) to (2.35, 31.65)
  point P7 (0, 34)
  point P3 (0, 20)
  point P2 (-2.35, 28.85)
  point P10 (2.35, 28.85)
  point P4 (0, 28.85)
  point P6 (0, 31.65)
  point P13 (0, 0)
  point P14 (0, 0)
  tangent L1 A1
  tangent A1 L2
  parallel L1 L2
  tangent A3 L2
  tangent L1 A3
  midpoint P7 A3
  midpoint P3 A1
  vertical L3
  coincident P2 L1
  coincident P10 L2
  coincident P4 L3
  equal A2 A3
  horizontal P2 P10
  vertical P6 P13
  dimension "d333_1" distance P3 P7 = 14 (= "PegH_3")
  dimension "d334_1" distance L1 L2 = 4.7 (= "PegW_3")
  dimension "d336_1" = 7.5 (= "SkadisSlotH_3 / 2")
  dimension "d341_1" distance A1 P14 = 20
extrude "Extrude1" new body sketch "Sketch1" profile of L1 A2 A3 L2 against normal blind 5.2 named "d342_1" (magnitude of "-PegD_3")
extrude "Extrude2" sketch "Sketch1" profile of L1 A1 A2 A3 L2 blind -5.2 (= "-PegD_3") named "d345_1"
sketch "Sketch3" plane through (0, 39.6118, 0) normal (0, -1, 0) x axis (1, 0, 0)
  line L1 (204, -40) -> (204, 60)
  line L2 (306, -40) -> (204, -40)
  line L3 (306, 60) -> (306, -40)
  line L4 (204, 60) -> (306, 60)
  line L5 (306, 50.6559) -> (204, 50.6559)
  line L6 (255, -40) -> (255, 60)
  circle C1 centre (255, 50.6559) radius 6.3441
  point P8 (255, 60)
  point P9 (255, -40)
  point P10 (255, 50.6559)
  midpoint L4 P8
  midpoint L2 P9
  midpoint L5 P10
position "Position2"
move "Move1"
rectangular_pattern "R-Pattern2" countU 2 (= "ceil(width / 40 / mm)") uSpaceDistance 40 vSpaceDistance 0
sketch "Text" plane through (0, 39.6118, 0) normal (0, -1, 0) x axis (1, 0, 0)
  dimension "d309" = 3
extrude "Extrude2" cut sketch "Text" against normal blind 2
sketch "Filename" plane through (0, 0, 0) normal (0, 1, 0) x axis (1, 0, 0)
  dimension "d312" = 3
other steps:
create_component "CreateComponent1"
create_component "CreateComponent2"
create_component "CreateComponent3"
create_component "CreateComponent5"
create_component "CreateComponent6"
create_component "CreateComponent3"
named bodies: "Wall anchor part", "Base plate with slot", "Screw plate", "Screw hole", "Screw hole (3)", "Screw hole (12)", "Screw plate (2)"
